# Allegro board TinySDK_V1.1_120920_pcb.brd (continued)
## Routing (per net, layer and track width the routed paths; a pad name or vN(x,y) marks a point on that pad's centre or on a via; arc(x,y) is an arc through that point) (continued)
XMMCCLK0: length 32.8
  BOTTOM w0.203: TINY210.B21 139,48.7 138.63,49.07 138.63,62.1 141.9,65.36 141.9,67.99 142.37,68.45 144.27,68.45 144.53,68.71 146.08,68.71 R41.1 149.46,72.1 CON10.5
XMMCCMD0: length 28.5
  BOTTOM w0.203: CON10.2 149.5,64.68 149.48,64.71 147.03,64.71 R42.1 146.09,64.15 144.5,64.15 139.04,58.69 139.04,49.23 139.91,48.36 139.91,45.91 TINY210.B22
XNRSTOUT: length 243.3
  TOP w0.203: U4.40 162.33,33.63 162.01,33.95 162.01,35.34 161.67,35.69 161.67,36.32 162.43,37.08 162.43,40.77 159,44.2 TINY210.B42 ; LCD4.32 10.48,85.77 13.12,85.77 19.18,79.71 19.18,77.72 20.42,76.48 28.68,76.48 29.34,75.82 29.34,72.52 31.5,70.36 42.42,70.36 v1(43.18,69.6) 47.93,64.85 70.28,64.85 84.02,78.59 91.7,78.59 91.81,78.48 LCD2.32 94.79,78.48 95.5,79.2 95.5,81.66 v1(95.76,81.92)
  BOTTOM w0.203: LCD1.32 44.32,56.12 44.32,62.23 44.63,62.54 44.63,65.73 44.42,65.94 44.42,65.94 44.32,66.05 LCD3.32 44.32,68.72 44.08,68.96 44,68.96 43.49,69.47 43.31,69.47 v1(43.18,69.6) ; v1(95.76,81.92) 98.81,81.92 103.12,77.6 103.12,74.21 104.14,73.2 104.14,52.54 102.83,51.24 102.83,46.73 110.96,38.6 126.45,38.6 128.57,40.72 129.63,40.72 130.94,42.02 136.05,42.02 136.7,42.67 146.51,42.67 146.67,42.82 154.71,42.82 155.83,43.94 157.94,43.94 TINY210.B42
XPWMTOUT0: length 209.6
  TOP w0.203: TINY210.A52 169,89.78 169.86,90.64 169.86,93.34 176.02,99.5 176.02,117.6 168.02,125.6 158.88,125.6 157.61,126.87 139.55,126.87 137.9,128.52 79.63,128.52 44.2,93.09 19.68,93.09 19.05,93.73 R6.2
XPWMTOUT1: length 179.5
  TOP w0.203: LCD4.30 10.48,83.77 12.5,83.77 17.74,78.52 17.74,72.89 22.79,67.84 38.5,67.84 v1(43.16,63.19) 43.48,62.87 70.79,62.87 85.72,77.8 91.37,77.8 91.69,77.48 LCD2.30 95.01,77.48 96.39,78.87 96.39,81.04 102.42,87.06 104.74,87.06 107.65,89.98 113.81,89.98 116.15,92.32 122.18,92.32 v1(123.4,93.54)
  BOTTOM w0.203: LCD1.30 43.32,52.97 43.48,53.14 43.48,62.82 43.32,63.03 v1(43.16,63.19) 43.31,63.34 43.31,63.89 43.32,63.9 43.32,65.12 43.46,65.26 43.46,65.81 43.32,65.95 43.32,67.06 LCD3.30 ; v1(123.4,93.54) 123.66,93.27 139.17,93.27 140.31,92.13 141.68,92.13 142.14,91.67 142.14,90.15 143,89.28 TINY210.A26
XSPICKL1: length 166.7
  TOP w0.203: v1(123.06,96.39) 122.72,96.74 121.44,96.74 120.85,96.14 115.83,96.14 115.51,96.14 115,95.63 114.51,95.15 114.2,94.83 113.52,94.16 103.16,94.16 97.62,88.62 88.81,88.62 86.07,85.88 82.01,85.88 79.67,83.54 67.46,83.54 61.59,89.41 61.59,94.41 62.84,95.66 62.97,95.66 SDIO.9
  BOTTOM w0.203: TINY210.B17 135.34,47.34 135.34,69.42 151.4,85.47 153.84,85.47 155.91,87.54 155.91,91.47 155.08,92.3 153.77,92.3 153.04,93.04 143.78,93.04 142.19,94.63 141.01,95.81 123.65,95.81 v1(123.06,96.39)
XSPICS1: length 175.3
  TOP w0.203: v1(124.08,96.47) 123.34,95.73 122.79,95.73 122.18,96.34 121.61,96.34 121.02,95.75 115.67,95.75 114.79,94.87 114.77,94.84 113.93,94.01 113.86,93.94 113.69,93.76 103.32,93.76 97.7,88.14 88.88,88.14 86.23,85.49 82.18,85.49 79.71,83.02 67.22,83.02 61.09,89.15 61.09,94.46 62.61,95.98 62.61,97.3 SDIO.10
  BOTTOM w0.203: TINY210.B18 135.91,45.91 135.91,47.66 135.86,47.71 135.86,69.36 151.47,84.96 154.26,84.96 157.91,88.62 157.91,91.36 157.23,92.05 156.36,92.05 155.52,92.89 154.15,92.89 153.61,93.43 143.94,93.43 142.58,94.8 141.18,96.2 124.35,96.2 v1(124.08,96.47)
XSPIMISO1: length 169.5
  TOP w0.203: SDIO.8 60.68,97.37 60.68,96.05 60.03,95.41 60.03,88.56 66.55,82.04 79.84,82.04 82.34,84.54 86.44,84.54 89.03,87.12 97.79,87.12 103.65,92.98 114.01,92.98 115.46,94.43 120.63,94.43 v1(121.88,95.68)
  BOTTOM w0.203: TINY210.B16 134.09,46.09 134.09,47.38 134.94,48.23 134.94,69.58 151.23,85.88 151.28,85.88 153.97,88.57 153.97,91.26 153.03,92.2 151.89,92.2 151.45,92.65 143.62,92.65 141.8,94.47 141.8,94.47 140.85,95.42 122.15,95.42 v1(121.88,95.68)
XSPIMOSI1: length 161.4
  TOP w0.203: SDIO.7 61.59,96.01 60.58,95 60.58,88.77 66.85,82.5 79.74,82.5 82.34,85.09 86.39,85.09 88.93,87.63 97.75,87.63 103.49,93.37 113.85,93.37 115.57,95.09 v1(120.14,95.09)
  BOTTOM w0.203: v1(120.14,95.09) 120.14,95.24 120.54,95.63 120.85,95.63 121.46,95.02 140.68,95.02 143.45,92.25 151.04,92.25 151.91,91.38 151.91,87.35 134.52,69.96 134.52,48.52 TINY210.B15
XUCTSN1: length 64
  TOP w0.203: CON2.2 78.69,20.65 78.69,20.65 86.3,28.26 92.7,28.26 93.81,29.38 93.81,29.39 94.43,30.01 94.45,30.01 108.76,44.33 108.76,47.68 110.13,49.05 v1(110.87,49.05)
  BOTTOM w0.203: TINY210.B6 121.68,43.68 113.35,43.68 111.91,45.11 111.91,48.01 v1(110.87,49.05)
XUHDM: length 83.4
  TOP w0.203: TINY210.A32 148.78,89.22 148.14,89.22 147.44,89.92 146.81,89.92 146.14,90.59 146.14,91.29 145.38,92.04 139.73,92.04 138.43,93.34 137.29,93.34 130.94,99.69 130.94,100.7 127.95,103.68 113.73,103.68 110.3,100.25 99.88,100.25 94.68,95.05 85.66,95.05 84.25,96.46 84.25,98.23 85.79,99.77 87.32,99.77 87.59,100.04 87.59,100.59 R96.2
XUHDP: length 85.3
  TOP w0.203: R82.2 88.05,100.34 88.05,99.85 87.51,99.31 85.98,99.31 84.71,98.04 84.71,96.65 85.85,95.5 94.49,95.5 99.69,100.71 110.11,100.71 113.54,104.14 128.14,104.14 131.39,100.89 131.39,99.88 137.48,93.8 138.62,93.8 139.92,92.5 145.57,92.5 145.96,92.12 147.11,92.12 147.86,91.36 147.86,90.14 148.14,89.86 150.14,89.86 TINY210.A34
XUODM: length 104.2
  TOP w0.203: MINIUSB1.2 103,9.26 103,17.16 112.95,27.11 112.95,44.91 115.73,47.69 115.73,48.86 116.15,49.28 116.32,49.28 v1(116.33,49.28)
  BOTTOM w0.203: TINY210.A31 148.01,90.01 148.01,86.86 128.19,67.04 128.19,56.37 122.85,51.03 117.58,51.03 116.33,49.78 116.33,49.29 v1(116.33,49.28)
XUODP: length 104.4
  TOP w0.203: 103.63,9.1 MINIUSB1.3 ; 103.63,9.1 103.46,9.27 103.46,16.97 113.41,26.92 113.41,44.7 116.19,47.48 116.19,47.85 117.37,49.03 v1(117.37,49.33) ; 103.63,9.1 103.63,9.09
  BOTTOM w0.203: v1(117.37,49.33) 117.37,49.48 118.47,50.57 123.04,50.57 128.65,56.18 128.65,66.85 148.59,86.79 148.59,87.3 149.99,88.69 149.99,89.99 TINY210.A33
XUOID: length 102.3
  TOP w0.203: v1(114.55,44.83) 114.05,44.32 114.05,24.89 104.43,15.28 104.43,9.1 MINIUSB1.4
  BOTTOM w0.203: v1(114.55,44.83) 114.55,45.09 115.57,46.1 115.57,50.52 116.76,51.71 121.33,51.71 126.7,57.08 126.7,67.13 146.2,86.64 146.2,88.5 146.09,88.62 146.09,90.09 TINY210.A29
XUOVBUS: length 111.6
  TOP w0.508: 98.68,22.61 98.68,23.88 104.6,29.79 110.06,29.79 112.39,32.13 112.39,45.14 114.91,47.65 v1(114.91,49.15) ; MINIUSB1.1 102.03,9.1 102.03,10.62 101.47,11.18
  TOP w0.762: 101.47,11.18 98.42,11.18 97.28,12.32 97.28,17.78 C52.1 98.81,19.3 98.81,20.95 C51.1 98.68,22.61
  BOTTOM w0.305: TINY210.A27 144.03,90.03 144.03,88.27
  BOTTOM w0.508: 144.03,88.27 144.03,85.24 126.15,67.36 126.15,66.49 126.14,66.47 126.14,57.29 121.12,52.27 116.28,52.27 114.94,50.93 114.94,49.17 v1(114.91,49.15)
XURTSN1: length 64
  TOP w0.203: v1(112.78,48.26) 112.65,48.39 110.11,48.39 109.16,47.43 109.16,44.16 108.56,43.56 94.61,29.62 94.6,29.62 94.21,29.23 94.21,29.21 92.86,27.87 86.54,27.87 80.69,22.02 80.69,19.18 CON2.1
  BOTTOM w0.203: TINY210.B5 121.92,45.92 121.92,44.63 121.36,44.07 113.51,44.07 112.52,45.06 112.52,48.01 v1(112.78,48.26)
XURXD0: length 114.7
  TOP w0.203: v1(45.85,15.75) 88.27,15.75 89.89,17.37 CON1.2 89.89,20.93 90.17,21.21 92.84,21.21 102.36,30.73 107.44,30.73 110.36,33.66 110.36,46.4 v1(111.12,47.16) ; 43.05,21.84 44.69,21.84 45.09,21.45 v1(45.09,21.34)
  BOTTOM w0.203: v1(45.09,21.34) 45.85,20.57 v1(45.85,15.75) ; TINY210.B8 122.82,42.82 112.88,42.82 110.49,45.21 110.49,46.53 v1(111.12,47.16)
XURXD1: length 72.6
  TOP w0.203: CON2.4 74.69,19.83 ; 74.69,19.83 76.83,21.97 78.82,21.97 83.41,26.56 86.57,29.72 90.87,29.72 107.67,46.51 107.67,48.48 v1(108.08,48.9) ; 74.69,19.83 74.69,19.83 74.69,19.18
  BOTTOM w0.203: v1(108.08,48.9) 108.08,46.02 112.09,42.01 124.01,42.01 TINY210.B10
XURXD2: length 183.5
  TOP w0.203: v1(58.8,85.85) 58.01,86.64 58.01,87.66 57.67,88 57.67,94.48 56.64,95.5 56.64,97.28 57.59,98.23 SDIO.4 ; v1(106.6,50.16) 106.6,48.39 102.49,44.27 102.49,42.57 93.18,33.26 74.49,33.26 71.62,30.39 69.63,30.39 63.47,24.23 CON3.2
  BOTTOM w0.203: TINY210.B12 127.24,43.24 127.04,43.24 126.16,42.35 126.11,42.35 124.95,41.2 111.75,41.2 106.6,46.34 v1(106.6,50.16) 106.6,51.38 104.93,53.06 104.93,73.62 104,74.55 104,78.75 96.77,85.98 73.66,85.98 72.62,87.02 71.74,87.02 71.57,86.86 59.57,86.86 58.8,86.09 v1(58.8,85.85)
XURXD3: length 114.8
  TOP w0.203: v1(105.28,49.91) 105.28,48.18 103.24,46.14 101.7,44.6 101.7,42.9 92.85,34.05 84.45,34.05 84.45,34.05 80.23,34.05 74.17,34.05 71.3,31.18 60.39,31.18 52.29,23.08 CON4.2 52.29,17.75 51.82,17.27 45.21,17.27 44.45,18.03 43.05,18.03
  BOTTOM w0.203: TINY210.B14 130.78,45 129.28,43.5 128.78,43.5 127.73,42.46 127.37,42.46 126.48,41.57 126.44,41.57 125.82,40.95 125.82,40.9 125.3,40.39 111.45,40.39 105.28,46.55 v1(105.28,49.91)
XUTXD0: length 113.1
  TOP w0.203: 43.05,20.57 44.58,20.57 v1(44.96,20.19) ; v1(44.83,15.75) 45.49,15.09 90.78,15.09 91.89,16.19 CON1.1 91.89,19.37 102.86,30.34 107.61,30.34 110.88,33.62 110.88,45.89 v1(111.25,46.25)
  BOTTOM w0.203: v1(44.83,15.75) 44.96,15.88 v1(44.96,20.19) ; v1(111.25,46.25) 111.38,46.13 111.38,45.09 113.23,43.23 122.52,43.23 123.95,44.66 123.95,45.26 125,46.31 TINY210.B7
XUTXD1: length 72.8
  TOP w0.203: CON2.3 76.69,20.56 76.69,20.56 77.6,21.46 78.87,21.46 86.18,28.78 92.66,28.78 93.42,29.54 93.42,29.56 94.27,30.4 94.28,30.4 108.23,44.35 108.23,48.08 v1(109.07,48.92)
  BOTTOM w0.203: v1(109.07,48.92) 109.07,45.74 112.39,42.42 123.71,42.42 126.09,44.79 126.09,45.38 127,46.29 TINY210.B9
XUTXD2: length 178.1
  TOP w0.203: CON3.1 65.47,23.68 74.66,32.87 93.45,32.87 107.26,46.69 v1(107.26,49.4) ; v1(58.67,87.12) 58.67,87.74 58.17,88.25 58.17,95.71 SDIO.3
  BOTTOM w0.203: v1(58.67,87.12) 58.9,87.12 59.03,87.25 71.41,87.25 71.57,87.41 73.24,87.41 74.23,86.42 97.09,86.42 104.39,79.12 104.39,74.71 105.32,73.79 105.32,53.3 107.26,51.36 v1(107.26,49.4) 107.26,46.28 111.94,41.61 124.8,41.61 125.95,42.75 125.99,42.75 126.88,43.64 126.93,43.64 128.09,44.79 128.09,45.38 129,46.29 TINY210.B11
XUTXD3: length 120.2
  TOP w0.203: v1(105.94,49.15) 105.94,48.29 103.41,45.75 102.09,44.44 102.09,42.74 93.01,33.66 74.33,33.66 73.87,33.19 71.46,30.78 61.26,30.78 54.29,23.81 CON4.1 54.29,17.27 53.66,16.64 44.83,16.64 44.45,17.02 42.09,17.02 41.45,17.65 41.45,18.97 41.78,19.3 43.05,19.3
  BOTTOM w0.203: v1(105.94,49.15) 105.94,46.45 111.6,40.79 125.1,40.79 126.27,41.96 126.32,41.96 127.21,42.85 127.57,42.85 128.61,43.9 129.12,43.9 129.91,44.69 129.91,45.21 131,46.29 TINY210.B13
XVHSYNC: length 198.8
  TOP w0.203: v1(100.46,61.21) 101.7,62.46 116.94,62.46 117.35,62.87 121.44,62.87 122.47,63.89 122.47,64.58 123.95,66.07 123.95,67.34 127.97,71.36 127.97,73.36 134.17,79.56 134.17,82.17 TINY210.A24 ; LCD2.35 89.99,79.98 v1(89.82,80.16) 89.55,80.42 84.15,80.42 69.76,66.03 49.37,66.03 v1(45.82,69.58) 45.82,69.94 44.22,71.54 31.99,71.54 30.52,73.01 30.52,76.31 26.94,79.88 22.35,79.88 13.36,88.87 11.59,88.87 LCD4.35
  BOTTOM w0.203: LCD1.35 45.82,52.83 45.82,62.06 45.89,62.13 45.89,66.14 45.82,66.21 LCD3.35 v1(45.82,69.58) ; v1(100.46,61.21) 99.5,62.17 96.37,62.17 90.96,67.59 90.96,79.02 v1(89.82,80.16)
XVVCLK: length 208
  TOP w0.203: TINY210.A25 142.09,90.09 142.09,88.77 136.33,83.02 136.33,77.81 125.35,66.83 125.35,64.72 123.55,62.92 123.55,62.08 122.43,60.96 117.86,60.96 117.02,61.8 102.31,61.8 v1(101.6,61.09) ; LCD4.36 10.5,89.79 13.08,89.79 22.5,80.37 27.2,80.37 30.91,76.66 30.91,73.17 32.15,71.93 44.78,71.93 v1(45.85,70.87) 46.74,69.98 46.74,69.6 49.91,66.42 69.6,66.42 83.99,80.82 90.5,80.82 v1(90.68,80.64) 90.84,80.48 LCD2.36
  BOTTOM w0.203: v1(45.85,70.87) 46.48,70.23 46.48,69.31 46.32,69.15 LCD3.36 46.32,66.27 LCD1.36 ; v1(101.6,61.09) 100.65,62.04 100.25,62.04 99.72,62.57 96.77,62.57 91.44,67.89 91.44,79.88 90.84,80.48 90.84,80.48 v1(90.68,80.64)
XVVD0: length 152.4
  TOP w0.203: TINY210.C25 120.09,77.09 118.61,77.09 113.28,71.75 109.01,71.75 105.67,68.41 100.62,68.41 98.4,66.19 98.4,65.21 97.64,64.45 97.62,64.44 97.6,64.43 96.49,64.43 96.03,63.98 LCD2.3 91.13,63.98 85.98,58.83 85.98,57.59 77.52,49.13 76.83,48.44 76.83,48.44 76.32,47.93 75.75,47.36 41.28,47.36 38.78,44.86 v1(29.34,44.86) 28.04,44.86 19.94,52.96 17.78,52.96 13.86,56.88 LCD4.3
  BOTTOM w0.203: v1(29.34,44.86) 29.34,46.99 29.81,47.47 LCD1.3 LCD3.3
XVVD1: length 152.5
  TOP w0.203: LCD4.4 10.62,57.91 13.84,57.91 18.4,53.35 20.43,53.35 28.27,45.52 v1(30,45.52) 30.18,45.34 38.71,45.34 41.23,47.87 75.7,47.87 76.66,48.83 85.47,57.64 85.47,58.88 91.07,64.48 LCD2.4 95.97,64.48 96.5,65 97.56,65 97.92,65.36 97.92,66.34 100.38,68.81 105.51,68.81 108.85,72.15 113.04,72.15 118.89,78 TINY210.C26
  BOTTOM w0.203: 30.31,67.36 LCD1.4 30.31,47.31 30,46.99 v1(30,45.52) ; 30.31,67.36 30.31,67.06 ; 30.31,67.36 LCD3.4
XVVD2: length 177.3
  TOP w0.203: TINY210.A20 137,87.34 124.08,74.42 124.08,68.58 122.36,66.86 116.01,66.86 114.31,65.16 112.02,65.16 110.12,63.26 101.03,63.26 v1(100.57,63.72) ; LCD4.5 13.64,58.88 18.41,54.1 20.45,54.1 20.99,53.56 28.37,46.18 30.64,46.18 v1(30.81,46) 30.97,45.85 38.48,45.85 40.89,48.26 75.54,48.26 84.95,57.67 84.95,58.91 91.02,64.98 LCD2.5 95.47,64.98 v1(95.68,65.19)
  BOTTOM w0.203: LCD1.5 30.81,51.31 ; 30.81,51.31 30.81,49.45 v1(30.81,46) ; 30.81,51.31 LCD3.5 ; v1(100.57,63.72) 100.54,63.75 98.81,63.75 97.37,65.19 v1(95.68,65.19)
XVVD3: length 178.7
  TOP w0.203: v1(100.88,64.58) 101.03,64.58 101.21,64.76 107.99,64.76 110.01,66.78 113.26,66.78 114.96,68.48 117.27,68.48 117.68,68.88 121.21,68.88 122.81,70.48 122.81,73.79 136.02,87 136.02,90.02 TINY210.A19 ; LCD4.6 10.53,59.82 15.29,59.82 21.16,53.95 28.27,46.84 31.27,46.84 31.6,46.51 v1(31.62,46.51) 31.78,46.35 37.08,46.35 40.35,49.62 76.34,49.62 84.35,57.63 84.35,58.87 89.26,63.77 89.26,63.78 90.96,65.48 LCD2.6 94.99,65.48 95.37,65.85 v1(97.16,65.85)
  BOTTOM w0.203: v1(97.16,65.85) 98.11,65.85 99.38,64.58 v1(100.88,64.58) ; v1(31.62,46.51) 31.31,46.82 LCD1.6 LCD3.6
XVVD4: length 173.4
  TOP w0.203: v1(101.35,65.53) 101.73,65.15 107.82,65.15 109.98,67.31 112.98,67.31 114.76,69.09 116.15,69.09 117.93,70.86 121.41,70.86 122.3,71.75 122.3,74.01 135,86.71 TINY210.A18 ; LCD4.7 11.6,60.88 12.32,61.59 14.02,61.59 15.4,60.21 15.45,60.21 21.32,54.34 21.86,54.34 28.96,47.24 31.82,47.24 32.05,47.02 v1(32.51,47.02) 32.77,46.76 36.86,46.76 40.11,50.01 76.17,50.01 83.76,57.59 83.76,58.83 88.86,63.94 88.86,63.94 90.9,65.98 LCD2.7 94.94,65.98 95.2,66.24 96.61,66.24 97.18,66.81 v1(97.31,66.81)
  BOTTOM w0.203: 31.81,67.36 LCD1.7 31.81,47.71 v1(32.51,47.02) ; 31.81,67.36 LCD3.7 ; 31.81,67.36 31.81,67.06 ; v1(101.35,65.53) 99.64,65.53 98.37,66.8 97.32,66.8 97.31,66.81 v1(97.31,66.81)
XVVD5: length 173.1
  TOP w0.203: LCD4.8 10.56,61.85 12.02,61.85 12.16,61.99 14.21,61.99 15.6,60.6 15.61,60.6 21.48,54.74 22.35,54.74 29.4,47.69 v1(33.13,47.69) 33.4,47.42 36.69,47.42 39.67,50.41 74.64,50.41 90.71,66.48 LCD2.8 94.88,66.48 95.04,66.64 96.21,66.64 98.71,69.14 99.67,69.14 101.8,71.27 101.8,71.59 101.8,72.89 104.11,75.2 111.64,75.2 118.14,81.69 118.14,82.58 118.47,82.91 128.37,82.91 133.99,88.53 133.99,89.98 TINY210.A17
  BOTTOM w0.203: LCD3.8 32.31,67.36 ; 32.31,67.36 LCD1.8 32.31,48.17 32.8,47.69 v1(33.13,47.69) ; 32.31,67.36 32.31,67.06
XVVD6: length 165.7
  TOP w0.203: TINY210.A16 133,88.12 128.2,83.32 118.32,83.32 117.74,82.74 117.74,81.86 111.58,75.69 104.05,75.69 101.64,73.29 101.41,73.06 101.41,71.43 99.51,69.53 98.54,69.53 96.1,67.08 94.93,67.08 94.82,66.98 LCD2.9 90.65,66.98 74.47,50.8 39.51,50.8 36.59,47.88 33.87,47.88 33.4,48.35 33.39,48.35 v1(32.97,48.77) 30.61,48.77 23.24,56.13 20.64,56.13 15.78,61 15.76,61 13.88,62.88 LCD4.9
  BOTTOM w0.203: LCD3.9 32.81,66.18 32.76,66.13 32.76,65.26 32.81,65.2 32.81,57.18 LCD1.9 32.81,48.93 v1(32.97,48.77)
XVVD7: length 170.5
  TOP w0.203: TINY210.A15 132.09,90.09 132.09,87.78 128.03,83.73 118.14,83.73 117.35,82.93 117.35,82.02 111.42,76.09 104.21,76.09 103.88,76.09 101.48,73.68 101.48,73.68 101.02,73.22 101.02,71.59 99.34,69.92 98.57,69.92 98.38,69.92 95.93,67.48 LCD2.10 90.59,67.48 75.31,52.2 40.21,52.2 36.4,48.39 34.39,48.39 v1(34.24,48.54) 34.1,48.68 34.1,48.74 33.4,49.43 30.71,49.43 23.5,56.64 22.23,56.64 14.98,63.89 10.6,63.89 LCD4.10
  BOTTOM w0.203: v1(34.24,48.54) 34.24,48.56 33.31,49.49 LCD1.10 33.31,54.02 33.4,54.1 33.4,57.4 33.31,57.49 33.31,65.26 33.15,65.42 33.15,65.97 33.31,66.13 LCD3.10
XVVD8: length 151.7
  TOP w0.203: v1(101.85,69.85) 102.49,69.85 103,70.36 106.3,70.36 108.52,72.58 112.92,72.58 118.06,77.72 118.06,78.35 118.62,78.91 119.91,78.91 TINY210.C27 ; v1(100.08,71.63) 99.42,71.63 96.59,68.8 95.23,68.8 94.91,68.48 LCD2.12 91.04,68.48 75.21,52.65 39.51,52.65 36.73,49.86 35.2,49.86 v1(35.18,49.89) 34.82,49.89 34.16,50.55 30.35,50.55 23.75,57.15 22.27,57.15 13.51,65.91 10.62,65.91 LCD4.12
  BOTTOM w0.203: v1(100.08,71.63) v1(101.85,69.85) ; LCD3.12 34.32,66.13 34.48,65.97 34.48,65.42 33.91,64.85 33.91,53.21 33.98,53.15 33.98,53.14 34.32,52.81 LCD1.12 34.32,50.39 34.82,49.89 v1(35.18,49.89)
XVVD9: length 142.8
  TOP w0.203: v1(102.31,70.71) 102.49,70.71 102.77,70.99 106.34,70.99 108.33,72.97 112.65,72.97 117.63,77.95 117.63,78.63 TINY210.C28 ; v1(100.33,72.64) 99.88,72.64 96.43,69.19 95.07,69.19 94.85,68.98 LCD2.13 90.98,68.98 75.09,53.09 34.97,53.09 v1(34.64,53.42) 33.85,54.2 28.68,54.2 25.22,57.66 22.32,57.66 13.1,66.88 LCD4.13
  BOTTOM w0.203: LCD3.13 34.82,66.18 34.87,66.13 34.87,65.26 34.42,64.8 34.42,53.64 v1(34.64,53.42) 34.82,53.24 LCD1.13 ; v1(102.31,70.71) 102.26,70.71 v1(100.33,72.64)
XVVD10: length 159.3
  TOP w0.203: TINY210.A14 131.03,88.97 131.03,87.28 127.87,84.12 117.75,84.12 116.39,82.75 116.1,82.75 110.95,77.6 104.27,77.6 96.26,69.59 94.9,69.59 94.8,69.48 LCD2.14 89.29,69.48 74.24,54.43 35.39,54.43 v1(35.08,54.74) 28.7,54.74 24.38,59.05 21.48,59.05 12.72,67.82 10.53,67.82 LCD4.14
  BOTTOM w0.203: LCD1.14 35.32,54.5 v1(35.08,54.74) 34.92,54.89 34.92,64.75 35.32,65.14 LCD3.14
XVVD11: length 157.9
  TOP w0.203: TINY210.A13 129.91,89.91 129.91,88.13 126.3,84.51 117.59,84.51 116.22,83.15 115.94,83.15 110.78,77.99 104.11,77.99 96.1,69.98 94.74,69.98 94.74,69.98 LCD2.15 89.24,69.98 74.11,54.85 36.16,54.85 v1(35.92,55.09) 35.61,55.4 28.67,55.4 24.51,59.56 23.34,59.56 14.03,68.88 LCD4.15
  BOTTOM w0.203: LCD1.15 35.82,54.32 35.92,54.43 v1(35.92,55.09) 35.43,55.58 35.43,64.71 35.82,65.09 LCD3.15
XVVD12: length 157.4
  TOP w0.203: LCD4.16 10.69,69.98 13.72,69.98 23.74,59.96 24.75,59.96 28.85,55.86 v1(36.41,55.86) 37.03,55.24 73.95,55.24 89.18,70.48 LCD2.16 96.04,70.48 104,78.44 110.67,78.44 115.78,83.54 116.06,83.54 117.43,84.91 126.12,84.91 129,87.79 TINY210.A12
  BOTTOM w0.203: LCD3.16 36.32,65.03 35.94,64.66 35.94,56.33 36.41,55.86 v1(36.41,55.86) 36.63,55.64 36.63,54.86 36.32,54.55 36.32,54.26 36.32,54.26 LCD1.16
XVVD13: length 156.5
  TOP w0.203: LCD4.17 13.37,70.88 23.8,60.45 24.89,60.45 28.74,56.61 v1(36.94,56.61) 37.91,55.64 73.78,55.64 89.12,70.98 LCD2.17 95.99,70.98 103.84,78.83 110.51,78.83 115.61,83.93 115.9,83.93 117.26,85.3 125.55,85.3 127.41,87.16 127.41,88.11 127.91,88.62 127.91,89.91 TINY210.A11
  BOTTOM w0.203: LCD1.17 36.82,54.49 37.11,54.78 37.11,56.44 v1(36.94,56.61) 36.43,57.12 36.43,64.59 36.82,64.97 LCD3.17
XVVD14: length 155.1
  TOP w0.203: TINY210.A10 127,87.33 125.36,85.7 117.1,85.7 115.73,84.33 115.45,84.33 110.37,79.25 103.7,79.25 95.93,71.48 LCD2.18 87.75,71.48 73.26,56.98 38.03,56.98 v1(37.09,57.93) 29.32,57.93 25.48,61.77 23.03,61.77 12.92,71.88 10.59,71.88 LCD4.18
  BOTTOM w0.203: LCD1.18 37.32,52.93 37.26,52.99 37.26,54.38 37.72,54.83 37.72,57.3 v1(37.09,57.93) 36.93,58.08 36.93,64.54 37.26,64.86 37.26,65.99 37.32,66.04 LCD3.18
XVVD15: length 154.4
  TOP w0.203: LCD4.19 12.49,72.88 23.13,62.23 25.65,62.23 29.18,58.71 37.24,58.71 v1(38.04,57.91) 38.57,57.38 73.1,57.38 87.7,71.98 LCD2.19 95.87,71.98 100.71,76.82 100.71,78.49 103.4,81.18 111.74,81.18 115.29,84.72 115.57,84.72 116.94,86.09 123.38,86.09 125.98,88.69 125.98,89.98 TINY210.A9
  BOTTOM w0.203: LCD1.19 37.82,52.99 37.66,53.15 37.66,54.17 38.16,54.67 38.16,57.79 v1(38.04,57.91) 37.44,58.51 37.44,64.49 37.66,64.7 37.66,65.82 37.82,65.98 37.82,66.93 37.82,66.93 LCD3.19
XVVD16: length 151.4
  TOP w0.203: v1(102.49,71.63) 104.23,73.37 112.49,73.37 117.2,78.08 117.2,79.49 118.79,81.09 120.09,81.09 TINY210.C29 ; LCD4.21 12.63,74.88 13.08,74.42 13.08,72.84 23.3,62.62 25.82,62.62 29.26,59.18 37.82,59.18 v1(38.18,58.82) 39.23,57.77 72.93,57.77 88.46,73.3 90.06,73.3 90.38,72.98 LCD2.21 95.83,72.98 99.05,76.2 99.06,76.2 v1(99.31,76.45)
  BOTTOM w0.203: v1(102.49,71.63) 99.31,74.8 v1(99.31,76.45) ; LCD1.21 38.82,53.13 38.98,53.3 38.98,54.45 38.82,54.61 38.82,58.18 ; 38.82,58.18 38.82,58.19 38.36,58.65 38.35,58.65 ; 38.82,58.18 v1(38.18,58.82) 37.92,59.08 37.92,64.22 38.98,65.28 38.98,65.82 38.82,65.98 LCD3.21
XVVD17: length 150.6
  TOP w0.203: TINY210.C30 111.8,74.8 104.65,74.8 v1(102.46,72.62) ; LCD4.22 10.48,75.77 11.95,75.77 11.96,75.76 12.63,75.76 13.59,74.8 13.59,72.89 23.46,63.02 25.98,63.02 26.44,62.56 29.29,59.7 38.24,59.7 v1(39.1,58.85) 39.78,58.17 72.77,58.17 88.3,73.69 90.23,73.69 90.44,73.48 LCD2.22 95.39,73.48 99.38,77.47 99.82,77.47 v1(99.95,77.34)
  BOTTOM w0.203: v1(99.95,77.34) 100.05,77.24 100.05,75.03 v1(102.46,72.62) ; LCD3.22 39.32,66.04 39.37,65.99 39.37,65.11 38.46,64.2 38.46,59.49 v1(39.1,58.85) 39.37,58.57 39.37,53.13 39.32,53.08 LCD1.22
XVVD18: length 151.8
  TOP w0.203: TINY210.A8 125,88.46 123.02,86.48 116.77,86.48 115.41,85.12 115.12,85.12 111.67,81.66 102.73,81.66 95.04,73.98 LCD2.23 90.5,73.98 90.39,74.09 86.74,74.09 72.18,59.52 39.78,59.52 39.74,59.56 39.72,59.56 v1(39.12,60.17) 38.45,60.83 30.1,60.83 26.54,64.39 22.86,64.39 13.98,73.27 13.98,75.68 12.78,76.88 LCD4.23
  BOTTOM w0.203: LCD1.23 39.82,59.47 v1(39.12,60.17) 39.12,64.16 39.82,64.86 39.82,67.36 ; LCD3.23 39.82,67.36 ; 39.82,67.36 39.82,66.93
XVVD19: length 155.9
  TOP w0.203: TINY210.A7 124.09,90.09 124.09,88.13 123.08,87.12 116.86,87.12 115.24,85.51 112.69,85.51 110.27,83.09 103.6,83.09 94.99,74.48 LCD2.24 90.55,74.48 90.55,74.48 86.58,74.48 72.02,59.92 40.32,59.92 v1(40.03,60.21) 38.81,61.42 30.07,61.42 26.71,64.78 23.02,64.78 14.38,73.43 14.38,76.05 12.66,77.77 10.48,77.77 LCD4.24
  BOTTOM w0.203: LCD1.24 40.32,59.92 v1(40.03,60.21) 39.62,60.61 39.62,63.95 40.32,64.64 40.32,67.36 ; 40.32,67.36 40.32,66.93 ; 40.32,67.36 LCD3.24
XVVD20: length 149.9
  TOP w0.203: TINY210.A6 121.53,87.53 116.71,87.53 115.08,85.9 112.52,85.9 110.18,83.56 103.51,83.56 94.93,74.98 LCD2.25 86.52,74.98 71.85,60.31 41.16,60.31 v1(40.39,61.09) 39.5,61.98 30.07,61.98 27.33,64.72 26.87,65.18 23.19,65.18 14.77,73.59 14.77,76.42 12.31,78.88 LCD4.25
  BOTTOM w0.203: LCD1.25 40.82,60.66 v1(40.39,61.09) 40.02,61.46 40.02,63.64 40.82,64.44 40.82,67.36 ; 40.82,67.36 40.82,66.93 ; 40.82,67.36 LCD3.25
XVVD21: length 153.8
  TOP w0.203: LCD4.26 10.47,79.76 11.22,79.76 11.22,79.77 11.95,79.77 11.96,79.76 12.44,79.76 15.16,77.04 15.16,73.76 23.35,65.57 27.03,65.57 27.72,64.88 30.11,62.49 40.27,62.49 v1(41.06,61.71) 42.06,60.71 71.69,60.71 86.46,75.48 LCD2.26 94.87,75.48 103.42,84.03 110.09,84.03 112.36,86.3 114.92,86.3 116.71,88.09 121.38,88.09 121.91,88.62 121.91,89.91 TINY210.A5
  BOTTOM w0.203: LCD3.26 41.32,64.18 40.51,63.37 40.51,62.25 v1(41.06,61.71) 41.32,61.45 LCD1.26
XVVD22: length 148.8
  TOP w0.203: LCD4.27 13.86,80.88 16.95,77.79 16.95,72.56 22.46,67.06 35.69,67.06 37.97,64.77 39.62,64.77 v1(41.27,63.12) 42.32,62.08 71.11,62.08 85.02,75.98 LCD2.27 94.82,75.98 103.65,84.82 105.67,84.82 108.53,87.68 114.69,87.68 116.92,89.91 120.09,89.91 TINY210.A4
  BOTTOM w0.203: LCD3.27 41.82,66.04 41.71,65.93 41.71,63.81 41.27,63.37 v1(41.27,63.12) 41.28,63.12 41.77,62.63 41.77,53.31 41.82,53.26 LCD1.27
XVVD23: length 153.3
  TOP w0.203: LCD4.28 10.47,81.76 11.22,81.76 11.22,81.77 11.95,81.77 11.96,81.76 13.74,81.76 17.35,78.16 17.35,72.72 22.62,67.45 37.88,67.45 41.74,63.59 41.74,63.59 v1(42.19,63.14) 42.86,62.47 70.95,62.47 84.96,76.48 LCD2.28 94.64,76.48 96.9,78.74 96.9,80.99 102.58,86.67 104.9,86.67 107.81,89.59 113.64,89.59 113.97,89.59 116.31,91.93 120.07,91.93 TINY210.A3
  BOTTOM w0.203: LCD1.28 42.32,53.32 42.16,53.47 42.16,63.12 v1(42.19,63.14) 42.1,63.23 42.1,65.77 42.32,65.98 42.32,66.67 LCD3.28
XVVDEN: length 172.2
  TOP w0.203: v1(121.16,93.54) 120.73,93.11 115.82,93.11 113.51,90.8 105.54,90.8 102.83,88.08 102.29,88.08 97.14,82.93 95.84,82.93 95,82.09 95,79.38 94.6,78.98 LCD2.33 91.86,78.98 91.86,78.98 83.86,78.98 70.11,65.24 48.55,65.24 44.32,69.47 v1(44.32,69.57) 44.3,69.57 43.12,70.75 31.66,70.75 29.73,72.68 29.73,75.98 28.84,76.87 20.92,76.87 19.57,78.22 19.57,79.87 12.56,86.88 LCD4.33
  BOTTOM w0.203: v1(44.32,69.57) 44.32,69.52 44.71,69.13 44.71,69.08 44.82,68.97 LCD3.33 44.82,66.1 45.1,65.82 45.1,62.45 45.02,62.38 44.82,62.17 LCD1.33 ; TINY210.A21 137.52,92.48 122.21,92.48 v1(121.16,93.54)
XVVSYNC: length 204.7
  TOP w0.203: LCD2.34 89.22,79.48 v1(89.06,79.64) 88.69,80.01 84.33,80.01 69.95,65.63 48.79,65.63 45.28,69.15 45.28,69.19 45.09,69.38 45.09,69.89 44.6,70.38 44.42,70.38 v1(44.32,70.48) 43.66,71.15 31.82,71.15 30.12,72.84 30.12,76.15 29,77.27 21.41,77.27 20.32,78.36 20.32,79.88 12.44,87.77 11.22,87.77 11.22,87.76 10.47,87.76 LCD4.34 ; v1(99.44,61.21) 101.09,62.87 115.32,62.87 117.35,64.9 121.79,64.9 123.19,66.29 123.19,67.13 127.38,71.33 127.38,73.66 133.78,80.06 133.78,82.33 139.91,88.47 139.91,89.91 TINY210.A23
  BOTTOM w0.203: LCD1.34 45.32,52.66 45.32,62.12 45.49,62.29 45.49,65.98 45.32,66.15 LCD3.34 45.32,69.15 44.98,69.48 44.98,70 44.6,70.38 44.42,70.38 v1(44.32,70.48) ; v1(89.06,79.64) 90.55,78.15 90.55,67.44 96.21,61.78 99.13,61.78 99.44,61.47 v1(99.44,61.21)
N490506: length 4.1
  TOP w0.203: U6.17 137.7,36.04 136.14,37.59 136.14,38.25 R57.2
N490846: length 3.3
  TOP w0.203: R58.2 135.41,37.44 137.31,35.54 U6.18
N563338: length 8.6
  TOP w0.254: C46.1 149.9,35.99 144.44,35.99 143.49,35.04 U6.6
N563659: length 3.1
  TOP w0.254: C45.1 144.53,36.7 143.36,35.54 U6.7
N565258: length 2.7
  TOP w0.254: U6.2 143.18,33.04 143.2,33.02 C44.1
N570115: length 2.9
  TOP w0.254: C43.1 144.26,35.18 143.62,34.54 U6.5
N579751: length 18.1
  TOP w0.279: U6.4 144.48,34.04 144.65,34.21 147.75,34.21 147.93,34.39 v1(148.08,34.39) ; C36.2 151,24.64 v1(150.75,24.38)
  BOTTOM w0.279: v1(148.08,34.39) 148.08,34.29 150.88,31.5 150.88,24.51 v1(150.75,24.38)
N580413: length 11.1
  TOP w0.279: R59.1 151.51,32.41 151.51,27.69 C36.1 C41.1 149.45,27.2 R62.2 R67.2
N605417: length 32.9
  TOP w0.279: SPK1.4 134.73,5.57 137.29,8.13 137.29,13.52 SPK1.3 135.74,15.14 134.75,16.13 134.75,16.76 135.13,17.14 138.68,17.14 141.1,19.56 141.1,22.61 143.03,24.54 R46.2 144.53,25.27 C34.1 143.31,27.25 C55.2
N617320: length 25
  TOP w0.279: C56.2 140.79,27.56 C33.1 139.06,26.67 139.98,25.76 R47.2 139.98,23.85 140.63,23.2 140.63,19.85 138.43,17.65 134.11,17.65 133.35,16.89 133.35,11.46 SPK1.1
N3676300: length 15.1
  TOP w0.203: S2.3 177.57,15.26 178.88,16.58 178.88,25.82 R2.2 R1.1
N3676952: length 86.1
  TOP w0.203: R2.1 176.81,29.46 176.4,29.46 175.15,30.72 175.15,34.09 178.32,37.26 178.32,48.17 176.83,49.66 132.86,49.66 132.61,49.4 131.87,49.4 131.21,50.06 130.57,50.06 129.39,48.88 121.4,48.88 120.02,47.5 120.02,45.85 119.17,45 TINY210.B2
N3684154: length 12
  TOP w0.203: S2.4 177.27,18.26 178.31,19.3 178.31,25.02 177.41,25.92 175.98,25.92 R3.2
N3805887: length 2.4
  TOP w0.203: LED_3.3.1 21.35,8.11 R4.2
N3869369: length 3.4
  TOP w0.203: U4.32 166.76,37.71 165.74,38.73 R7.1
N3921053: length 11
  TOP w0.254: Y1.1 155.06,33.92 156.21,32.77 159.38,32.77 160.16,33.54 C19.1 161.68,32.14 U4.43
N3921204: length 10.1
  TOP w0.254: U4.44 160.41,31.63 C20.1 159.52,32.26 155.45,32.26 155.06,31.87 Y1.2
N3925254: length 10.1
  TOP w0.203: R8.1 157.96,25.15 157.96,26.64 158.88,27.56 161.68,27.56 162.18,28.06 163.31,28.06 164.21,28.96 164.59,28.96 164.76,28.79 U4.1
N3968686: length 2.8
  TOP w0.559: C25.1 168.82,23.46 R25.2 R24.2
N3970814: length 2.8
  TOP w0.559: R29.2 R26.2 163.23,23.41 C26.1
N3982722: length 28.4
  TOP w0.203: LAN1.9 154.53,7.94 154.53,8.67 155.79,9.93 155.79,12.67 153.41,15.05 153.41,21.21 155.32,23.12 155.32,25.12 158.73,28.52 R20.2
N3983324: length 25.7
  TOP w0.203: R21.2 175.51,24.99 175.51,23.62 174.37,22.48 174.37,20.82 172.1,18.54 172.1,14.11 165.41,7.42 165.41,6.51 LAN1.12
N4027687: length 3.6
  TOP w0.203: Q2.B 15.5,95.6 R16.2 R6.1
N4771984: length 8.6
  TOP w0.254: C42.2 149.61,34.16 148.91,34.16 148.45,33.71 147.7,33.71 147.65,33.76 144.84,33.76 144.63,33.54 U6.3
N5234173: length 2.5
  TOP w0.203: R92.2 139.08,38.82 U6.15
N5390728: length 3.1
  TOP w0.279: C55.1 141.59,30.75 U6.31
N5390947: length 2.7
  TOP w0.279: C56.1 140.59,29.85 U6.29
N5424123: length 5.7
  TOP w0.279: U6.27 139.58,30.36 139.06,29.84 138.43,29.84 C58.1 137.34,28.75 C57.2
N6095373: length 3.5
  TOP w0.254: U8.1 35.43,26.92 C39.2
N6095738: length 3
  TOP w0.254: U8.3 C39.1
N6103030: length 8.5
  TOP w0.254: C40.2 34.54,27.81 38.91,27.81 39.24,27.48 39.24,25.91 38.99,25.65 U8.2
N6103395: length 3.7
  TOP w0.254: C49.2 35.94,20.57 U8.6
N6105619: length 3.3
  TOP w0.254: C61.1 35.05,23.11 U8.4
N6105986: length 3.4
  TOP w0.254: C61.2 35.31,21.84 U8.5
N6195963: length 20
  TOP w0.559: Q2.C 17.9,100.84 17.9,117.13 BUZZER1.2
N9607388: length 7.4
  TOP w0.203: U11.30 88.28,107.94 88.3,107.92 88.3,107.35 87.53,106.58 R136.1 87.75,105.83 87.75,103.77 R96.1
N9607392: length 6.7
  TOP w0.203: R82.1 88.2,103.72 88.2,105.76 R135.1 88.76,106.84 88.76,107.92 88.78,107.94 U11.31
N9607432: length 13.4
  TOP w0.254: Y3.2 91.82,99.03 91.82,101.98 C95.1 92.21,103.26 91.53,103.94 91.53,105.96 90.91,106.58 R130.2 90.36,107.02 90.36,107.25 89.78,107.82 U11.33
N9607572: length 83.4
  TOP w0.254: C86.1 94.87,111.76 U11.5 ; C93.1 84.96,112.65 84.96,112.27 85.47,111.76 U11.23 ; U11.15 88.78,115.69 C87.1 ; U11.29 87.78,107.98 87.38,107.57 86.74,107.57 ; C94.1 93.83,108.31 93.01,108.31 92.98,108.28 92.41,108.28 92.38,108.31 91.46,108.31 91.28,108.49 U11.36 ; U11.10 91.28,117.19 C88.1
  TOP w0.559: 85.47,117.44 85.12,117.09 C80.1 C89.1 83.57,119.51 84.33,120.27 88.69,120.27 89.3,120.88 91.84,120.88 93.27,119.46 93.27,119.05 93.22,119 ; 85.47,117.44 85.59,117.44 85.63,117.4 86.56,117.4 86.63,117.47 C87.1 ; 85.47,117.44 v1(85.47,116.33) ; 93.22,119 92.33,118.11 92.21,118.11 C88.1 ; 93.22,119 R118.1 ; C82.1 85.47,106.94 v1(86.11,107.57) 86.74,107.57 ; v1(84.91,114.43) 84.14,113.66 C93.1 ; C94.1 94.62,108.99 95.65,107.96 95.65,107.38 95.94,107.09 v1(95.94,106.78) ; v1(98.81,105.54) 98.98,105.71 98.98,108.3 99.19,108.5 99.19,109.47 97.77,110.89 97.32,110.89 97.21,111 95.76,111 95,111.76 C86.1
  BOTTOM w0.559: v1(86.11,107.57) 86.49,107.95 86.49,112.85 v1(84.91,114.43) 84.91,114.5 84.96,114.55 84.96,115.82 v1(85.47,116.33) 85.85,115.95 88.52,115.95 93.65,110.82 93.69,110.82 94.18,110.33 94.18,110.29 95.63,108.84 95.63,107.19 95.94,106.88 v1(95.94,106.78) 96.16,106.78 97.28,105.66 98.68,105.66 v1(98.81,105.54)
N9607910: length 14.3
  TOP w0.254: Y3.1 89.65,97.65 91.29,99.29 91.29,102.13 C81.1 90.81,103.12 R130.1 89.92,105.89 89.92,107.06 89.28,107.69 U11.32
N9607998: length 8.1
  TOP w0.203: R119.1 80.88,108.28 82.99,108.28 83.7,107.57 C85.1 84.84,108.45 84.84,109.35 85.25,109.76 U11.27
N9608162: length 5.4
  TOP w0.203: U11.34 90.28,108.09 90.94,107.43 91.96,107.43 C84.1 C90.1
N9608206: length 4.6
  TOP w0.203: U11.14 89.28,116.39 90.05,117.15 C92.1 C91.1
N9608680: length 6.4
  TOP w0.203: USBH1.2 162.59,116.2 162.59,114.99 161.65,114.05 161.65,113.59 R89.2 R91.1
N9608700: length 6.4
  TOP w0.203: USBH1.3 162.13,116.2 162.13,115.18 161.19,114.24 161.19,113.59 R90.2 R93.1
N9608868: length 6
  TOP w0.203: USBH2.2 144.81,116.2 144.81,113.54 R95.2 R94.1
N9608880: length 6
  TOP w0.203: R99.1 R97.2 144.35,113.65 144.35,116.2 USBH2.3
N9609084: length 6.4
  TOP w0.203: USBH3.2 120.24,13.6 120.24,16.52 R110.2 R109.1
N9609088: length 6.3
  TOP w0.203: R113.1 R112.2 120.7,16.66 120.7,13.6 USBH3.3
N9616349: length 19.3
  TOP w0.203: R81.1 52.5,90.75 50.86,90.75 48.07,87.96 41.97,87.96 40.22,86.2 40.22,84.59 40.05,84.42 ; CON8.36 40.05,84.42 ; 40.05,84.42 40.05,84.42 40.05,83.19
N9616353: length 18.5
  TOP w0.203: 40.85,84.42 40.85,83.19 ; 40.85,84.42 40.67,84.59 40.67,86.01 42.16,87.5 48.26,87.5 51.05,90.3 52.55,90.3 R80.1 ; 40.85,84.42 40.85,84.41 CON8.38
N9617073: length 21.2
  TOP w0.203: PERST_N.1 18.41,87.5 18.41,86.23 23.1,81.55 28.87,81.55 29.13,81.28 34.04,81.28 34.45,81.69 34.45,82.55 34.45,82.55 CON8.22
N9617077: length 28.2
  TOP w0.203: R76.1 54.71,82.17 57.28,82.17 57.52,82.41 57.52,87.38 57.15,87.76 51.44,87.76 49.81,86.13 43.33,86.13 42.45,85.24 42.45,83.69 42.45,83.69 CON8.42
N9617165: length 2
  TOP w0.203: D4.2 54.89,79.19 R76.2
N9621622: length 15.7
  TOP w0.762: L6.1 166.88,96.39 C104.1 167.26,99.82 166.5,100.58 AVIN.2 AVIN.1
N9621696: length 3.7
  TOP w0.203: U9.28 150.37,97.05 R142.2 R145.2
N9622060: length 7.7
  TOP w0.305: C53.2 157.35,96.39 157.35,97.6 155.21,99.74 155.21,100.19 154.53,100.87 U9.1
N9622080: length 7
  TOP w0.305: U9.2 154.8,101.37 155.7,100.47 155.7,99.95 158.37,97.28 C63.2
N9622122: length 7
  TOP w0.762: C63.1 C53.1 161.42,95.38 C65.1 161.95,94.84 R51.1 163.73,94.87 L6.2
N9622404: length 8
  TOP w0.254: U9.5 155.71,102.87 C109.1 160.48,101.73 Y2.1
N9622412: length 8.4
  TOP w0.254: Y2.2 158.9,103.76 C108.1 156.45,103.37 U9.6
N9622484: length 7.3
  TOP w0.203: U9.30 151.37,98.56 152.27,97.66 154.31,97.66 C112.2 C110.2
N9622488: length 4.4
  TOP w0.203: U9.29 150.87,98.05 C111.2 C110.1
N9622590: length 3
  TOP w0.203: R137.1 148.53,97.5 148.53,97.5 148.68,97.65 148.68,97.65 149.37,98.34 U9.26
N9622630: length 3.6
  TOP w0.203: U9.25 148.87,98.58 147.94,97.65 147.41,97.65 147.26,97.5 147.26,97.5 R138.1
N9633247: length 21.8
  TOP w0.279: MIC2.4 MIC2.1 142.37,21.59 145.16,24.38 145.19,24.38 R67.1
N9633353: length 12.2
  TOP w0.279: MIC2.2 MIC2.3 144.37,20.99 MIC1.1

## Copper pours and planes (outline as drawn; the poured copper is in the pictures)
AGND on BOTTOM: 130.68,1.02 129.92,1.78 129.92,18.54 128.78,19.68 128.78,31.78 130.42,33.41 130.42,36.31 130.68,36.58 136.78,36.58 138.3,35.05 138.3,32.64 138.56,32.38 141.99,32.38 142.37,32.77 142.37,35.69 142.49,35.81 143.13,35.81 144.65,37.34 151.26,37.34 152.02,36.58 152.02,23.62 148.46,20.07 148.46,1.4 148.08,1.02
GND on TOP (solid shape): 19.67,54.76 19.69,54.65 19.59,54.58 18.61,54.58 14.04,59.16 14.02,59.27 14.11,59.33 15.09,59.33
GND on TOP (solid shape): 22.51,59.71 22.53,59.6 22.44,59.54 21.68,59.54 13,68.22 12.98,68.33 13.07,68.39 13.83,68.39
GND on TOP (solid shape): 71.19,95.21 71.23,95.29 71.32,95.31 71.42,95.28 73.46,93.25 73.46,92.75 73.44,92.71 73.41,92.7 72.25,92.7 71.19,93.76
GND on TOP (solid shape): 74.46,51.71 74.55,51.65 74.53,51.54 74.27,51.28 40.22,51.28 40.13,51.35 40.15,51.46 40.41,51.71
GND on TOP (solid shape): 83.1,58.19 83.21,58.21 83.27,58.12 83.27,57.79 75.97,50.5 75.65,50.5 75.56,50.56 75.58,50.67
GND on TOP (solid shape): 91.42,56.76 91.51,56.69 91.49,56.58 78.95,44.04 77.94,44.04 77.85,44.11 77.87,44.22 90.41,56.76
GND on TOP (solid shape): 105.65,69.88 105.74,69.81 105.72,69.7 105.31,69.29 102.86,69.29 102.76,69.35 102.79,69.46 103.2,69.88
GND on TOP (solid shape): 106.61,47.71 106.72,47.73 106.78,47.64 106.78,46.89 103.14,43.25 103.03,43.22 102.97,43.32 102.97,44.07
GND on TOP (solid shape): 106.67,89.92 106.76,89.86 106.74,89.75 104.54,87.55 103.82,87.55 103.72,87.61 103.74,87.72 105.95,89.92
GND on TOP (solid shape): 113.39,26.22 113.5,26.24 113.56,26.15 113.56,25.09 104.12,15.65 104.01,15.62 103.94,15.72 103.94,16.77
GND on TOP (solid shape): 126.32,88.28 126.4,88.21 126.49,88.15 126.51,88.13 126.52,88.11 126.52,87.53 125.16,86.18 124.4,86.18 124.31,86.24 124.33,86.35 126.27,88.29 126.31,88.29
GND on TOP (solid shape): 127.75,56.79 127.84,56.73 127.82,56.62 124.01,52.81 122.59,52.81 122.5,52.87 122.52,52.98 126.34,56.79
GND on TOP (solid shape): 131.88,100.74 131.94,100.83 132.05,100.81 138.4,94.46 138.42,94.35 138.33,94.28 137.68,94.28 131.88,100.08
GND on TOP (solid shape): 24.34,41.4 24.35,41.34 24.3,41.31 24.27,41.31 21.54,44.04 20.46,44.04 20.42,44.06 20.41,44.09 20.41,44.55 20.42,44.59 20.46,44.6 21.14,44.6
GND on TOP (solid shape): 26.22,42.19 26.23,42.13 26.18,42.1 26.15,42.1 21.15,47.09 20.46,47.09 20.42,47.11 20.41,47.14 20.41,47.6 20.42,47.64 20.46,47.65 20.76,47.65
GND on TOP (solid shape): 27.35,42.58 27.36,42.53 27.31,42.49 27.28,42.49 21.15,48.62 20.46,48.62 20.42,48.63 20.41,48.67 20.41,49.12 20.42,49.16 20.46,49.17 20.76,49.17
GND on TOP (solid shape): 28.48,42.97 28.49,42.92 28.44,42.89 28.41,42.89 21.15,50.14 20.46,50.14 20.42,50.15 20.41,50.19 20.41,50.65 20.42,50.68 20.46,50.7 20.76,50.7
GND on TOP (solid shape): 21.39,56.79 21.42,56.68 21.32,56.62 20.84,56.62 15.98,61.48 15.96,61.48 14.21,63.23 14.19,63.34 14.28,63.4 14.78,63.4
GND on TOP (solid shape): 75.48,49.14 75.58,49.07 75.56,48.96 75.34,48.74 40.69,48.74 38.28,46.33 37.99,46.33 37.89,46.39 37.91,46.5 40.55,49.14
GND on TOP (solid shape): 88.21,71 88.31,70.93 88.29,70.82 73.58,56.12 38.11,56.12 37.9,56.33 37.88,56.44 37.97,56.5 73.46,56.5 87.95,71
GND on TOP (solid shape): 110.89,80.7 110.98,80.63 110.96,80.52 110.17,79.73 103.5,79.73 101.37,77.6 101.26,77.58 101.19,77.67 101.19,78.29 103.6,80.7
GND on TOP (solid shape): 114.11,85.03 114.2,84.96 114.18,84.85 111.47,82.14 103.58,82.14 103.49,82.21 103.51,82.32 103.8,82.61 110.47,82.61 112.89,85.03
GND on TOP (solid shape): 116.54,78.86 116.65,78.88 116.71,78.79 116.71,78.28 112.29,73.85 104.62,73.85 104.53,73.91 104.55,74.02 104.85,74.32 112,74.32
GND on TOP (solid shape): 23.12,41.09 23.14,40.98 23.05,40.92 22.78,40.92 21.18,42.52 20.46,42.52 20.42,42.53 20.41,42.57 20.41,43.03 20.42,43.06 20.46,43.08 21.14,43.08
GND on TOP (solid shape): 130.4,88.12 130.42,88.16 130.47,88.16 130.52,88.13 130.54,88.11 130.55,88.09 130.55,87.48 127.67,84.6 127.31,84.6 127.22,84.67 127.24,84.78 130.4,87.93
GND on TOP (solid shape): 29.9,60.35 38.25,60.35 38.33,60.27 38.34,60.22 38.29,60.19 29.49,60.19 26.92,62.76 26.18,63.5 23.66,63.5 23.43,63.73 23.4,63.84 23.5,63.91 26.34,63.91
GND on TOP (solid shape): 107.31,72.89 107.4,72.82 107.38,72.71 106.14,71.48 103.33,71.48 103.25,71.51 103.22,71.58 103.23,71.66 103.23,71.68 103.24,71.7 104.43,72.89
GND on TOP (solid shape): 107.57,45.74 107.68,45.76 107.75,45.66 107.75,44.55 94.08,30.89 94.07,30.89 92.94,29.76 92.94,29.74 92.46,29.26 91.34,29.26 91.25,29.32 91.27,29.43
GND on TOP (solid shape): 115.99,73.78 116.11,73.8 116.17,73.71 116.17,73.52 112.28,69.63 108.96,69.63 107.37,68.05 106.24,68.05 106.14,68.11 106.17,68.22 109.21,71.27 113.48,71.27
GND on TOP (solid shape): 133.38,102.92 133.38,101.91 140.64,94.64 141.41,94.64 141.97,94.08 141.99,93.97 141.9,93.9 140.97,93.9 129.55,105.32 129.53,105.43 129.63,105.49 130.81,105.49
GND on TOP (solid shape): 16.47,77.59 16.47,73.38 16.41,73.28 16.3,73.3 15.65,73.96 15.65,77.24 12.64,80.25 12.48,80.25 12.44,80.27 12.44,80.32 12.47,80.37 12.48,80.39 12.51,80.39 13.66,80.39
GND on TOP (solid shape): 30.41,48.29 32.4,48.29 32.42,48.28 32.44,48.26 32.45,48.2 32.41,48.17 29.6,48.17 22.55,55.22 21.68,55.22 21.42,55.48 21.4,55.59 21.5,55.65 23.04,55.65
GND on TOP (solid shape): 87.28,73.6 87.38,73.54 87.35,73.43 72.57,58.65 39.98,58.65 39.84,58.79 39.83,58.87 39.83,58.93 39.85,59.01 39.93,59.04 72.38,59.04 86.94,73.6
GND on TOP (solid shape): 116.69,82.38 116.8,82.4 116.87,82.31 116.87,82.22 111.22,76.57 104.22,76.57 104.17,76.57 104.08,76.63 104.1,76.74 104.47,77.11 111.15,77.11 116.3,82.27 116.59,82.27
GND on TOP (solid shape): 137.86,102.67 142.1,102.67 142.14,102.65 142.15,102.62 142.15,102.04 142.16,102.04 142.16,100.86 142.15,100.83 142.11,100.81 141.81,100.81 141.39,100.39 139.53,100.39 133.03,106.89 133.01,107 133.11,107.06 133.46,107.06
GND on TOP (solid shape): 85.55,75.5 85.65,75.43 85.63,75.32 71.49,61.19 42.26,61.19 41.81,61.64 41.8,61.65 41.8,61.68 41.8,61.73 41.79,61.8 41.8,61.83 41.81,61.83 41.84,61.85 41.88,61.83 42.12,61.59 71.31,61.59 85.22,75.5
GND on TOP (solid shape): 37.77,64.29 39.42,64.29 40.53,63.18 40.54,63.08 40.51,63.01 40.44,62.98 30.31,62.98 28.21,65.08 27.23,66.05 23.55,66.05 23.2,66.4 23.18,66.51 23.27,66.57 35.49,66.57
GND on TOP (solid shape): 88.81,60.98 88.92,61 88.98,60.9 88.98,58.37 76.61,45.99 52.87,45.99 52.15,46.7 52.13,46.81 52.22,46.88 75.95,46.88 77.03,47.96 78,48.93 86.46,57.39 86.46,58.63
GND on TOP (solid shape): 65.26,88.18 65.29,88.17 68.74,84.72 68.76,84.61 68.67,84.54 67.88,84.54 64.49,87.93 64.49,87.96 64.53,88.04 64.62,88.06 64.93,88.05 65.22,88.17
GND on TOP (solid shape): 152.64,93.73 154.31,93.73 155.13,94.54 156.5,94.54 156.83,94.2 156.85,94.09 156.76,94.03 156.44,94.03 155.93,93.52 150.88,93.52 150.5,93.9 149.27,93.9 149.19,93.94 149.17,94.03 149.18,94.05 149.63,94.5 151.32,94.5 151.32,94.51 151.35,94.54 151.83,94.54
GND on TOP (solid shape): 29.12,57.45 36.51,57.45 36.53,57.44 36.54,57.43 36.57,57.4 36.61,57.31 36.56,57.24 36.47,57.18 36.39,57.11 36.38,57.1 36.36,57.09 28.94,57.09 25.09,60.93 24,60.93 23.82,61.12 23.79,61.23 23.89,61.29 25.28,61.29
GND on TOP (solid shape): 123.73,99.94 123.75,99.94 123.77,99.93 123.8,99.9 123.83,99.79 123.73,99.72 121.92,99.72 121.33,99.13 114.17,99.13 112.28,97.23 101.76,97.23 96.33,91.81 85.92,91.81 82.17,88.06 81.34,88.06 81.31,88.08 81.29,88.11 81.29,88.45 85.32,92.48 96.24,92.48 101.35,97.59 111.64,97.59 113.99,99.94
GND on TOP (solid shape): 155.6,88.15 155.65,88.06 155.65,86.69 151.49,82.52 141.04,82.52 141.01,82.55 140.99,82.67 141.09,82.73 142.97,82.73 144.98,84.73 151.71,84.73 154.99,88.01 155.01,88.01 155.26,88.04 155.5,88.15
GND on TOP (solid shape): 105.98,95.08 106.05,95.05 106.08,94.97 106.07,94.86 106.08,94.76 106.06,94.68 105.98,94.64 102.96,94.64 97.42,89.1 88.61,89.1 85.87,86.36 83.78,86.36 83.69,86.43 83.71,86.54 86.79,89.61 97.23,89.61 102.7,95.08
GND on TOP (solid shape): 70.77,29.91 70.86,29.85 70.84,29.73 64.99,23.88 64.99,21.01 64.97,20.98 64.94,20.96 64.26,20.96 64.26,20.8 64.21,20.71 64.11,20.71 64.05,20.75 63.98,20.78 63.96,20.8 63.95,20.83 63.95,24.03 69.83,29.91
GND on TOP (solid shape): 90.63,17.65 90.68,17.56 90.68,17.4 91.35,17.4 91.39,17.38 91.4,17.35 91.4,16.39 90.58,15.57 89.02,15.57 88.92,15.63 88.94,15.74 90.37,17.17 90.37,17.53 90.38,17.56 90.4,17.58 90.46,17.61 90.52,17.65
GND on TOP (solid shape): 117.84,72.04 117.95,72.07 118.01,71.97 118.05,71.73 118.15,71.5 118.15,71.4 118.06,71.35 117.73,71.35 115.95,69.57 115.61,69.57 115.52,69.63 115.54,69.74
GND on TOP (solid shape): 117.95,64.41 118.03,64.37 118.05,64.28 118.02,63.88 118.14,63.5 118.14,63.4 118.06,63.35 117.15,63.35 116.74,62.94 116.32,62.94 116.23,63 116.25,63.11 117.55,64.41
GND on TOP (solid shape): 80.92,91.36 81.02,91.3 81,91.19 79.15,89.34 79.15,88.8 78.94,88.6 77.82,88.6 77.75,88.63 77.72,88.71 77.71,88.9 77.65,89.09 77.65,89.1 77.65,89.37 77.66,89.41 77.7,89.42 77.81,89.42 77.81,91.31 77.83,91.35 77.86,91.36
GND on TOP (solid shape): 117.94,66.38 118.02,66.34 118.04,66.25 118.02,65.88 118.13,65.53 118.13,65.43 118.04,65.38 117.15,65.38 115.12,63.35 111.14,63.35 111.04,63.41 111.07,63.52 112.22,64.67 114.51,64.67 116.21,66.38
GND on TOP (solid shape): 117.94,54.65 118.06,54.65 118.15,54.6 118.15,54.5 118.01,54.05 118.1,53.59 118.09,53.49 118.01,53.44 115.27,53.44 113.49,55.22 113.47,55.33 113.56,55.4 117.19,55.4
GND on TOP (solid shape): 117.96,89.43 118.04,89.39 118.06,89.3 118.01,89 118.06,88.7 118.04,88.61 117.96,88.57 116.51,88.57 114.72,86.78 112.16,86.78 109.89,84.51 106.29,84.51 106.2,84.57 106.22,84.68 108.73,87.2 114.89,87.2 117.12,89.43
GND on TOP (solid shape): 123.42,73.72 123.53,73.74 123.6,73.65 123.6,68.78 122.16,67.35 121.94,67.35 121.85,67.4 121.85,67.5 121.99,68.1 121.74,68.66 121.72,68.7 121.74,68.73 123.29,70.29 123.29,73.59
GND on TOP (solid shape): 135.67,102.84 135.75,102.82 138.82,99.74 138.82,98.74 141.78,98.74 141.82,98.73 141.83,98.69 141.83,96.2 141.82,96.16 141.78,96.14 141.06,96.14 134.73,102.47 134.73,102.53 134.75,102.56 134.79,102.58 134.8,102.58 135.23,102.57 135.59,102.81
GND on TOP (solid shape): 176.4,44.03 176.45,44.12 176.55,44.12 176.71,44.05 176.89,44.02 176.92,44 176.94,43.96 176.94,37.67 176.02,36.75 175.91,36.73 175.84,36.82 175.84,38.81 174.49,38.81 174.39,38.87 174.41,38.98 174.73,39.3 174.73,41.71 176.4,43.38
GND on TOP (solid shape): 10.07,46.63 11.33,45.36 16.07,45.36 16.15,45.33 16.17,45.24 16.15,45.09 16.17,44.93 16.15,44.84 16.07,44.81 11.33,44.81 10.09,46.04 10.08,46.07 10.05,46.33 9.93,46.55 9.92,46.61 9.97,46.64
GND on TOP (solid shape): 54.71,87.27 54.75,87.26 54.76,87.22 54.76,83.85 56.99,83.85 57.02,83.83 57.04,83.79 57.04,82.7 57.02,82.67 56.99,82.65 54.51,82.65 53.46,81.6 52.47,81.6 52.47,80.73 52.4,80.63 52.29,80.65 51.07,81.87 51.06,81.91 51.07,81.95 52.97,83.85 54.33,83.85 54.33,87.22 54.35,87.26 54.38,87.27
GND on TOP (solid shape): 135.68,83 135.79,83.02 135.85,82.92 135.85,78.01 124.87,67.03 124.87,64.92 123.06,63.12 123.06,62.28 122.23,61.44 121.99,61.44 121.91,61.49 121.9,61.59 121.99,62.06 121.84,62.53 121.83,62.54 121.83,62.58 122.95,63.69 122.95,64.38 124.43,65.87 124.43,67.14 128.45,71.16 128.45,73.16 134.65,79.36 134.65,81.97
GND on TOP (solid shape): 21.69,79.86 21.72,79.77 21.66,79.69 21.13,79.22 20.97,78.52 20.97,78.5 20.96,78.48 20.92,78.46 20.88,78.48 20.8,78.56 20.8,80.08 12.64,88.25 12.48,88.25 12.44,88.28 12.44,88.33 12.46,88.37 12.48,88.39 12.51,88.39 13.16,88.39
GND on TOP (solid shape): 52.16,92.61 52.19,92.59 52.21,92.56 52.21,91.29 52.19,91.25 52.16,91.24 50.66,91.24 47.87,88.44 41.77,88.44 39.73,86.4 39.73,84.79 39.55,84.6 35.96,84.6 35.92,84.61 35.91,84.65 35.91,84.77 35.91,84.78 35.88,85.46 35.31,85.82 35.22,85.89 35.24,86 35.53,86.29 35.53,86.92 37.66,89.05 46.81,89.05 50.36,92.61
GND on TOP (solid shape): 34.62,49.41 35.15,49.15 35.7,49.36 35.71,49.37 35.73,49.38 36.46,49.38 36.55,49.31 36.53,49.2 36.2,48.87 34.93,48.87 34.9,48.88 34.62,49.17 34.26,49.28 34.24,49.28 33.6,49.91 30.91,49.91 30.84,49.98 30.83,50.03 30.88,50.06 33.96,50.06
GND on TOP (solid shape): 117.95,68.4 118.03,68.36 118.05,68.27 118.02,67.88 118.15,67.5 118.15,67.4 118.06,67.35 115.81,67.35 114.11,65.64 111.82,65.64 109.92,63.74 101.36,63.74 101.32,63.75 101.31,63.79 101.3,63.85 101.28,63.92 101.28,63.95 101.3,63.97 101.44,64.1 101.54,64.25 101.56,64.27 101.58,64.27 108.19,64.27 110.21,66.29 113.46,66.29 115.16,68 117.47,68 117.88,68.4
GND on TOP (solid shape): 157.55,44.12 157.6,44.03 157.6,43.9 158.9,42.6 158.9,42.2 158.89,42.17 158.85,42.15 158.56,42.15 158.56,38.87 159.84,38.87 159.93,38.78 159.95,38.67 159.86,38.61 157.94,38.61 157.94,37.17 157.87,37.08 157.76,37.1 156.57,38.3 156.57,43.96 156.61,44.04 156.7,44.06 157.08,44.01 157.45,44.12
GND on TOP (solid shape): 28.48,53.72 33.65,53.72 33.89,53.49 33.9,53.47 33.9,53.45 34.12,52.9 34.67,52.68 34.7,52.68 34.77,52.6 38.54,52.6 38.64,52.54 38.62,52.43 36.53,50.34 35.78,50.34 35.76,50.35 35.74,50.36 35.34,50.6 34.88,50.56 34.85,50.55 34.82,50.57 34.36,51.03 30.55,51.03 24.58,57 24.56,57.11 24.65,57.18 25.02,57.18
GND on TOP (solid shape): 8.79,45.54 8.89,45.52 9.12,45.4 9.38,45.36 9.41,45.36 10.93,43.84 16.07,43.84 16.15,43.8 16.17,43.72 16.15,43.56 16.17,43.4 16.15,43.32 16.07,43.28 9.85,43.28 9.42,43.71 9.42,43.73 9.16,44.25 8.6,44.42 8.52,44.44 8.48,44.52 8.48,45.01 8.49,45.03 8.5,45.05 8.65,45.24 8.73,45.46
GND on TOP (solid shape): 42,22.56 42.04,22.48 41.72,21.84 42.04,21.21 41.72,20.57 42.04,19.94 42,19.86 41.97,19.83 41.93,19.8 41.92,19.79 41.9,19.79 41.58,19.79 41.46,19.66 41.35,19.64 41.29,19.74 41.29,22.26 41.62,22.59 41.96,22.59
GND on TOP (solid shape): 50.01,85.65 50.11,85.67 50.18,85.59 50.48,85.05 51.05,84.84 51.2,84.84 51.3,84.77 51.27,84.66 49.8,83.19 49.39,83.19 49.01,83.56 49.01,83.58 48.73,84.09 48.2,84.33 48.18,84.33 47.52,84.99 46.45,84.99 46.1,84.89 45.84,84.61 45.81,84.6 42.98,84.6 42.94,84.61 42.93,84.65 42.93,85.04 43.53,85.65
GND on TOP (solid shape): 104.62,49.49 104.71,49.45 104.74,49.41 104.78,49.37 104.8,49.35 104.8,49.33 104.8,48.38 101.22,44.8 101.22,43.1 100.15,42.03 100.04,42.01 99.97,42.1 99.97,46.16 100.05,46.48 99.97,46.81 99.97,48.95 100.04,49.16 100.04,49.38 100.07,49.46 100.14,49.49 103.18,49.49 103.2,49.48 103.22,49.46 103.87,49.05 104.54,49.44
GND on TOP (solid shape): 30.79,78.38 43.62,78.38 45.14,76.86 50.22,76.86 50.31,76.77 50.33,76.66 50.24,76.6 47.76,76.6 47.76,72.92 47.75,72.89 47.71,72.87 46.78,72.87 46.75,72.89 46.73,72.92 46.73,75.4 42.76,75.4 42.72,75.41 42.71,75.45 42.71,75.83 42.35,76.18 42.35,76.19 41.66,76.68 40.96,76.19 40.96,76.18 40.59,75.81 40.59,75.45 40.57,75.41 40.54,75.4 31.84,75.4 31.8,75.41 31.79,75.45 31.79,77.23 28.43,80.58 28.42,80.64 28.47,80.67 28.5,80.67
GND on TOP (solid shape): 170.34,44.26 170.57,44.11 170.82,44.03 170.85,44.01 170.87,43.98 170.87,43.89 170.83,43.81 170.75,43.79 170.08,43.47 170.03,42.73 170.03,41.93 169.67,41.57 169.56,41.55 169.49,41.64 169.49,42.11 167.82,42.11 167.82,40.86 167.76,40.77 167.65,40.79 167.38,40.95 167.07,40.99 166.99,41.02 166.95,41.09 166.95,42.32 167.91,43.27 169.29,43.27 170.29,44.27 170.33,44.27
GND on TOP (solid shape): 91.47,47.23 91.5,47.22 91.52,47.16 91.52,45.86 91.99,45.21 92.76,45.45 92.84,45.5 93.47,45.17 94.11,45.5 94.19,45.45 94.22,45.42 94.25,45.39 94.26,45.37 94.26,45.35 94.26,44.9 93.67,44.31 90.81,44.31 90.77,44.33 90.75,44.36 90.75,47.18 90.77,47.22 90.81,47.23
GND on TOP (solid shape): 162.12,31.13 162.16,31.11 162.17,31.08 162.19,30.99 162.22,30.91 162.23,30.89 162.17,30.64 162.23,30.39 162.17,30.14 162.23,29.89 162.17,29.64 162.22,29.42 162.22,29.39 162.19,29.36 162.01,29.2 161.88,29 161.32,28.44 161.06,28.44 160.98,28.48 160.96,28.57 161.01,28.83 160.97,29.08 160.96,29.11 160.98,29.14 161.01,29.16 161.15,29.16 161.15,30.81 161.14,30.81 161.11,30.84 161.11,31.08 161.13,31.11 161.17,31.13
